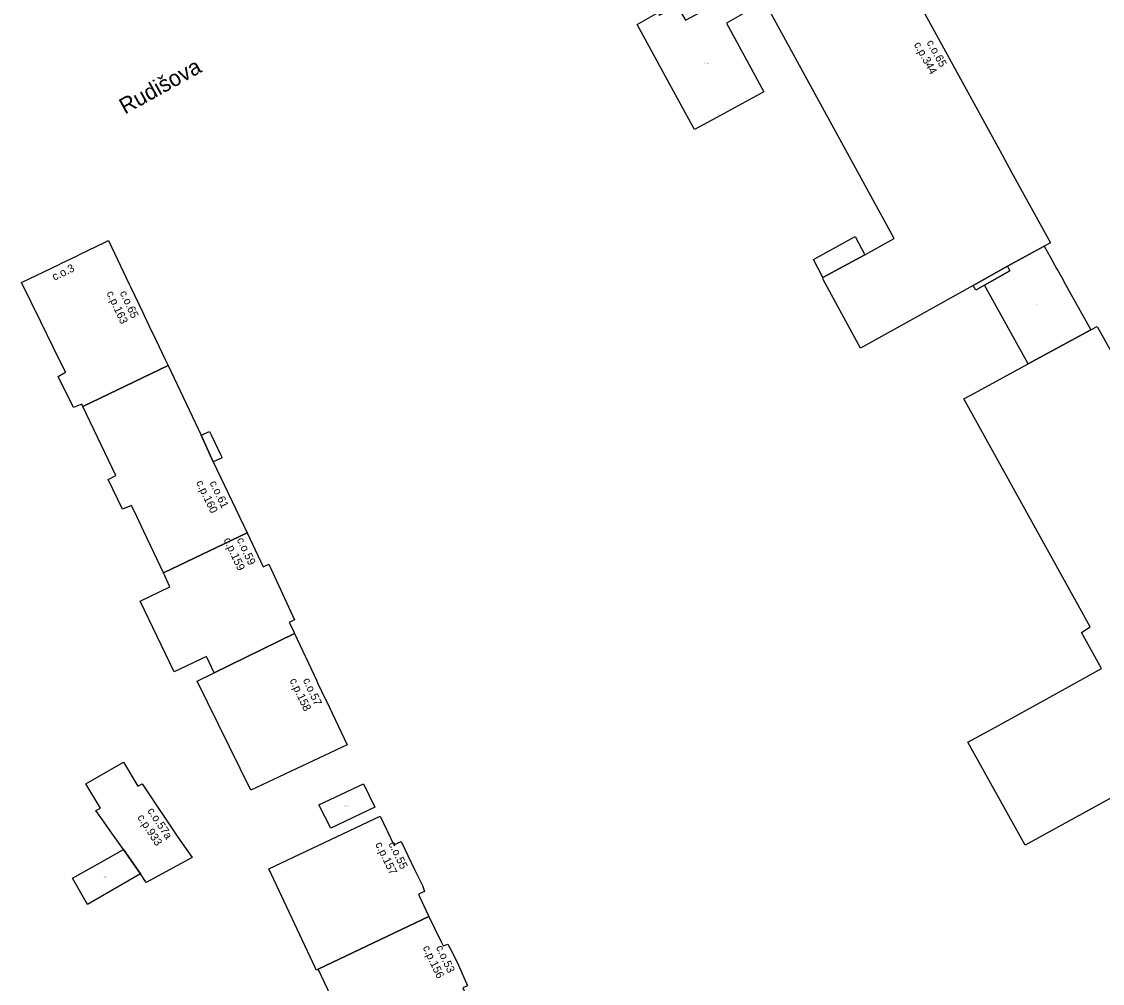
# Model space of a CAD drawing. Extents: x -600391 to -599491, y -1160176 to -1159402.
# Drawn here: x -600170.9 to -600035.9, y -1159941 to -1159820.9 of the extents above; entities that cross this region are included whole.
import ezdxf

# ---------------------------------------------------------------- set-up
doc = ezdxf.new("R2010")
doc.units = 0
for name, color, linetype in [('Level 10', 7, 'Continuous'), ('Level 11', 7, 'Continuous'), ('Level 12', 7, 'Continuous'), ('Level 24', 7, 'Continuous'), ('Level 25', 7, 'Continuous'), ('Level 61', 7, 'Continuous'), ('Level 62', 7, 'Continuous')]:
    doc.layers.add(name, color=color, linetype=linetype)

msp = doc.modelspace()

# ---------------------------------------------------------------- linework, layer by layer
at = {"layer": 'Level 61'}
for points in [[(-600079.35, -1159819.1), (-600082.86, -1159821.07)], [(-600063.12, -1159845.77), (-600078.08, -1159818.36)], [(-600058.78, -1159818.63), (-600048.7, -1159837.01)], [(-600094.02, -1159821.24), (-600091.37, -1159819.77)], [(-600088.71, -1159830.95), (-600094.02, -1159821.24)], [(-600082.86, -1159821.07), (-600080.07, -1159826.22)], [(-600080.07, -1159826.22), (-600078.2, -1159829.67)], [(-600078.2, -1159829.67), (-600084.15, -1159832.9)], [(-600086.85, -1159834.36), (-600088.71, -1159830.95)], [(-600084.15, -1159832.9), (-600086.85, -1159834.36)], [(-600048.7, -1159837.01), (-600047.23, -1159839.69)], [(-600047.23, -1159839.69), (-600042.39, -1159848.51)], [(-600061.89, -1159848), (-600063.12, -1159845.77)], [(-600071.97, -1159850.6), (-600066.76, -1159847.73)], [(-600066.76, -1159847.73), (-600065.55, -1159850.01)], [(-600065.55, -1159850.01), (-600061.89, -1159848)], [(-600163.65, -1159850), (-600160.45, -1159848.45)], [(-600160.45, -1159848.45), (-600160.03, -1159848.25)], [(-600160.03, -1159848.25), (-600157.44, -1159853.69)], [(-600043.18, -1159848.94), (-600047.74, -1159851.46)], [(-600047.74, -1159851.46), (-600043.18, -1159848.94)], [(-600042.39, -1159848.51), (-600043.18, -1159848.94)], [(-600043.18, -1159848.94), (-600042.43, -1159850.28)], [(-600165.88, -1159851.08), (-600163.96, -1159850.15)], [(-600163.96, -1159850.15), (-600163.65, -1159850)], [(-600070.83, -1159852.86), (-600071.97, -1159850.6)], [(-600070.83, -1159852.86), (-600065.55, -1159850.01)], [(-600065.55, -1159850.01), (-600070.83, -1159852.86)], [(-600042.43, -1159850.28), (-600041.62, -1159851.73)], [(-600170.88, -1159853.49), (-600166.2, -1159851.23)], [(-600166.2, -1159851.23), (-600165.88, -1159851.08)], [(-600052.02, -1159853.85), (-600047.74, -1159851.46)], [(-600047.74, -1159851.46), (-600052.02, -1159853.85)], [(-600047.45, -1159852.03), (-600050.61, -1159853.81)], [(-600050.61, -1159853.81), (-600047.45, -1159852.03)], [(-600047.74, -1159851.46), (-600047.45, -1159852.03)], [(-600047.45, -1159852.03), (-600047.74, -1159851.46)], [(-600041.62, -1159851.73), (-600041.47, -1159851.99)], [(-600041.47, -1159851.99), (-600040.81, -1159853.16)], [(-600070.77, -1159853.12), (-600070.83, -1159852.86)], [(-600066.1, -1159861.67), (-600070.77, -1159853.12)], [(-600040.81, -1159853.16), (-600040.67, -1159853.43)], [(-600040.67, -1159853.43), (-600037.35, -1159859.41)], [(-600168.48, -1159858.39), (-600170.88, -1159853.49)], [(-600157.44, -1159853.69), (-600157.28, -1159854.02)], [(-600157.28, -1159854.02), (-600155.74, -1159857.25)], [(-600052.02, -1159853.85), (-600058.91, -1159857.7)], [(-600051.72, -1159854.44), (-600052.02, -1159853.85)], [(-600050.61, -1159853.81), (-600051.72, -1159854.44)], [(-600045.16, -1159863.66), (-600050.61, -1159853.81)], [(-600155.74, -1159857.25), (-600155.57, -1159857.62)], [(-600166.88, -1159861.66), (-600168.48, -1159858.39)], [(-600155.57, -1159857.62), (-600154.61, -1159859.63)], [(-600058.91, -1159857.7), (-600066.1, -1159861.67)], [(-600154.61, -1159859.63), (-600154.46, -1159859.95)], [(-600154.46, -1159859.95), (-600152.96, -1159863.1)], [(-600037.35, -1159859.41), (-600045.16, -1159863.66)], [(-600045.16, -1159863.66), (-600037.35, -1159859.41)], [(-600037.35, -1159859.41), (-600036.54, -1159858.98)], [(-600036.54, -1159858.98), (-600029.35, -1159871.89)], [(-600165.39, -1159864.7), (-600166.88, -1159861.66)], [(-600152.59, -1159863.87), (-600163.24, -1159868.98)], [(-600163.24, -1159868.98), (-600152.59, -1159863.87)], [(-600152.96, -1159863.1), (-600152.8, -1159863.44)], [(-600152.8, -1159863.44), (-600152.59, -1159863.87)], [(-600152.59, -1159863.87), (-600148.47, -1159872.54)], [(-600051.89, -1159867.31), (-600045.16, -1159863.66)], [(-600166.31, -1159865.22), (-600165.39, -1159864.7)], [(-600164.39, -1159869.1), (-600166.31, -1159865.22)], [(-600053.19, -1159868.02), (-600051.89, -1159867.31)], [(-600037.41, -1159896.51), (-600053.19, -1159868.02)], [(-600163.38, -1159868.66), (-600164.39, -1159869.1)], [(-600163.24, -1159868.98), (-600163.38, -1159868.66)], [(-600159.12, -1159877.59), (-600163.24, -1159868.98)], [(-600148.47, -1159872.54), (-600147.41, -1159872.09)], [(-600147.41, -1159872.09), (-600147.2, -1159872.53)], [(-600146.95, -1159875.9), (-600148.47, -1159872.54)], [(-600148.47, -1159872.54), (-600146.95, -1159875.9)], [(-600147.2, -1159872.53), (-600146, -1159875.04)], [(-600146, -1159875.04), (-600145.82, -1159875.38)], [(-600145.82, -1159875.38), (-600146.95, -1159875.9)], [(-600146.95, -1159875.9), (-600142.71, -1159884.74)], [(-600160.05, -1159878.1), (-600159.12, -1159877.59)], [(-600158.3, -1159881.81), (-600160.05, -1159878.1)], [(-600157.17, -1159881.34), (-600158.3, -1159881.81)], [(-600156.5, -1159882.73), (-600157.17, -1159881.34)], [(-600155.62, -1159884.58), (-600156.5, -1159882.73)], [(-600153.15, -1159889.76), (-600155.62, -1159884.58)], [(-600142.71, -1159884.74), (-600153.15, -1159889.76)], [(-600153.15, -1159889.76), (-600142.71, -1159884.74)], [(-600142.71, -1159884.74), (-600140.71, -1159889)], [(-600152.38, -1159891.51), (-600153.15, -1159889.76)], [(-600140.71, -1159889), (-600140.02, -1159888.65)], [(-600140.02, -1159888.65), (-600136.8, -1159895.63)], [(-600156.06, -1159893.29), (-600152.38, -1159891.51)], [(-600151.82, -1159902.1), (-600156.06, -1159893.29)], [(-600136.8, -1159895.63), (-600137.46, -1159895.97)], [(-600137.46, -1159895.97), (-600136.9, -1159897.07)], [(-600038.5, -1159897.19), (-600037.41, -1159896.51)], [(-600136.78, -1159897.34), (-600146.82, -1159902.24)], [(-600146.82, -1159902.24), (-600136.78, -1159897.34)], [(-600136.9, -1159897.07), (-600136.78, -1159897.34)], [(-600136.78, -1159897.34), (-600134.02, -1159903.25)], [(-600036.01, -1159901.71), (-600038.5, -1159897.19)], [(-600147.81, -1159900.21), (-600151.82, -1159902.1)], [(-600146.82, -1159902.24), (-600147.81, -1159900.21)], [(-600040.15, -1159903.99), (-600036.01, -1159901.71)], [(-600148.94, -1159903.29), (-600146.82, -1159902.24)], [(-600142.24, -1159916.89), (-600148.94, -1159903.29)], [(-600134.02, -1159903.25), (-600133.91, -1159903.48)], [(-600133.91, -1159903.48), (-600132.92, -1159905.56)], [(-600042.46, -1159905.27), (-600040.15, -1159903.99)], [(-600132.92, -1159905.56), (-600132.82, -1159905.77)], [(-600132.82, -1159905.77), (-600130.21, -1159911.22)], [(-600046.85, -1159907.69), (-600042.46, -1159905.27)], [(-600049.25, -1159909.02), (-600046.85, -1159907.69)], [(-600052.69, -1159910.92), (-600049.25, -1159909.02)], [(-600130.21, -1159911.22), (-600142.24, -1159916.89)], [(-600045.53, -1159923.79), (-600052.69, -1159910.92)], [(-600162.86, -1159916.1), (-600158.15, -1159913.41)], [(-600158.15, -1159913.41), (-600156.35, -1159916.42)], [(-600027.98, -1159914.13), (-600045.53, -1159923.79)], [(-600161.04, -1159919.14), (-600162.86, -1159916.1)], [(-600156.35, -1159916.42), (-600155.83, -1159916.12)], [(-600155.83, -1159916.12), (-600154.16, -1159918.62)], [(-600133.75, -1159918.74), (-600128.2, -1159916.13)], [(-600128.2, -1159916.13), (-600126.76, -1159919.01)], [(-600161.59, -1159919.46), (-600161.04, -1159919.14)], [(-600160.57, -1159920.9), (-600161.59, -1159919.46)], [(-600154.16, -1159918.62), (-600152.79, -1159920.64)], [(-600132.26, -1159921.65), (-600133.75, -1159918.74)], [(-600126.76, -1159919.01), (-600132.26, -1159921.65)], [(-600159.8, -1159921.99), (-600160.57, -1159920.9)], [(-600152.79, -1159920.64), (-600151.37, -1159922.76)], [(-600140, -1159926.73), (-600126.12, -1159920.16)], [(-600126.12, -1159920.16), (-600124.38, -1159923.72)], [(-600158.37, -1159924.01), (-600159.8, -1159921.99)], [(-600151.37, -1159922.76), (-600149.6, -1159925.33)], [(-600124.38, -1159923.72), (-600123.49, -1159923.33)], [(-600123.49, -1159923.33), (-600121.81, -1159926.81)], [(-600161.03, -1159925.93), (-600158.17, -1159924.3)], [(-600158.17, -1159924.3), (-600158.37, -1159924.01)], [(-600156.89, -1159926.1), (-600158.17, -1159924.3)], [(-600158.17, -1159924.3), (-600156.89, -1159926.1)], [(-600164.53, -1159927.88), (-600161.03, -1159925.93)], [(-600156.05, -1159927.37), (-600156.89, -1159926.1)], [(-600156.89, -1159926.1), (-600156.05, -1159927.37)], [(-600149.6, -1159925.33), (-600155.33, -1159928.45)], [(-600156.05, -1159927.37), (-600162.67, -1159931.18)], [(-600155.33, -1159928.45), (-600156.05, -1159927.37)], [(-600134.22, -1159939.05), (-600140, -1159926.73)], [(-600121.81, -1159926.81), (-600120.83, -1159928.82)], [(-600162.67, -1159931.18), (-600164.53, -1159927.88)], [(-600120.83, -1159928.82), (-600120.57, -1159929.54)], [(-600120.57, -1159929.54), (-600121.33, -1159929.88)], [(-600121.33, -1159929.88), (-600121.2, -1159930.2)], [(-600121.2, -1159930.2), (-600120.35, -1159931.98)], [(-600120.02, -1159932.67), (-600133.83, -1159939.26)], [(-600133.83, -1159939.26), (-600120.02, -1159932.67)], [(-600120.35, -1159931.98), (-600120.02, -1159932.67)], [(-600120.02, -1159932.67), (-600118.52, -1159935.78)], [(-600118.52, -1159935.78), (-600118.25, -1159936.35)], [(-600118.25, -1159936.35), (-600117.63, -1159936.13)], [(-600117.63, -1159936.13), (-600117.07, -1159937.23)], [(-600117.07, -1159937.23), (-600116.33, -1159938.77)], [(-600134.1, -1159939.39), (-600134.22, -1159939.05)], [(-600133.83, -1159939.26), (-600134.1, -1159939.39)], [(-600127.84, -1159951.9), (-600133.83, -1159939.26)], [(-600116.33, -1159938.77), (-600115.19, -1159941.35)]]:
    msp.add_lwpolyline(points, dxfattribs=at)
at = {"layer": 'Level 62'}
for points in [[(-600079.35, -1159819.1), (-600082.86, -1159821.07), (-600080.07, -1159826.22), (-600078.2, -1159829.67), (-600084.15, -1159832.9), (-600086.85, -1159834.36), (-600088.71, -1159830.95), (-600094.02, -1159821.24), (-600091.37, -1159819.77), (-600091.21, -1159820.1), (-600089, -1159818.94), (-600087.98, -1159820.71), (-600080.6, -1159816.74), (-600079.35, -1159819.1)], [(-600058.78, -1159818.63), (-600048.7, -1159837.01), (-600047.23, -1159839.69), (-600042.39, -1159848.51), (-600043.18, -1159848.94), (-600047.74, -1159851.46), (-600052.02, -1159853.85), (-600058.91, -1159857.7), (-600066.1, -1159861.67), (-600070.77, -1159853.12), (-600070.83, -1159852.86), (-600065.55, -1159850.01), (-600061.89, -1159848), (-600063.12, -1159845.77), (-600078.08, -1159818.36)], [(-600066.76, -1159847.73), (-600065.55, -1159850.01), (-600070.83, -1159852.86), (-600071.97, -1159850.6), (-600066.76, -1159847.73)], [(-600163.24, -1159868.98), (-600163.38, -1159868.66), (-600164.39, -1159869.1), (-600166.31, -1159865.22), (-600165.39, -1159864.7), (-600166.88, -1159861.66), (-600168.48, -1159858.39), (-600170.88, -1159853.49), (-600166.2, -1159851.23), (-600165.88, -1159851.08), (-600163.96, -1159850.15), (-600163.65, -1159850), (-600160.45, -1159848.45), (-600160.03, -1159848.25), (-600157.44, -1159853.69), (-600157.28, -1159854.02), (-600155.74, -1159857.25), (-600155.57, -1159857.62), (-600154.61, -1159859.63), (-600154.46, -1159859.95), (-600152.96, -1159863.1), (-600152.8, -1159863.44), (-600152.59, -1159863.87), (-600163.24, -1159868.98)], [(-600045.16, -1159863.66), (-600050.61, -1159853.81), (-600047.45, -1159852.03), (-600047.74, -1159851.46), (-600043.18, -1159848.94), (-600042.43, -1159850.28), (-600041.62, -1159851.73), (-600041.47, -1159851.99), (-600040.81, -1159853.16), (-600040.67, -1159853.43), (-600037.35, -1159859.41), (-600045.16, -1159863.66)], [(-600050.61, -1159853.81), (-600051.72, -1159854.44), (-600052.02, -1159853.85), (-600047.74, -1159851.46), (-600047.45, -1159852.03), (-600050.61, -1159853.81)], [(-600027.98, -1159914.13), (-600045.53, -1159923.79), (-600052.69, -1159910.92), (-600049.25, -1159909.02), (-600046.85, -1159907.69), (-600042.46, -1159905.27), (-600040.15, -1159903.99), (-600036.01, -1159901.71), (-600038.5, -1159897.19), (-600037.41, -1159896.51), (-600053.19, -1159868.02), (-600051.89, -1159867.31), (-600045.16, -1159863.66), (-600037.35, -1159859.41), (-600036.54, -1159858.98), (-600029.35, -1159871.89)], [(-600142.71, -1159884.74), (-600153.15, -1159889.76), (-600155.62, -1159884.58), (-600156.5, -1159882.73), (-600157.17, -1159881.34), (-600158.3, -1159881.81), (-600160.05, -1159878.1), (-600159.12, -1159877.59), (-600163.24, -1159868.98), (-600152.59, -1159863.87), (-600148.47, -1159872.54), (-600146.95, -1159875.9), (-600142.71, -1159884.74)], [(-600148.47, -1159872.54), (-600147.41, -1159872.09), (-600147.2, -1159872.53), (-600146, -1159875.04), (-600145.82, -1159875.38), (-600146.95, -1159875.9), (-600148.47, -1159872.54)], [(-600146.82, -1159902.24), (-600147.81, -1159900.21), (-600151.82, -1159902.1), (-600156.06, -1159893.29), (-600152.38, -1159891.51), (-600153.15, -1159889.76), (-600142.71, -1159884.74), (-600140.71, -1159889), (-600140.02, -1159888.65), (-600136.8, -1159895.63), (-600137.46, -1159895.97), (-600136.9, -1159897.07), (-600136.78, -1159897.34), (-600146.82, -1159902.24)], [(-600146.82, -1159902.24), (-600136.78, -1159897.34), (-600134.02, -1159903.25), (-600133.91, -1159903.48), (-600132.92, -1159905.56), (-600132.82, -1159905.77), (-600130.21, -1159911.22), (-600142.24, -1159916.89), (-600148.94, -1159903.29), (-600146.82, -1159902.24)], [(-600155.83, -1159916.12), (-600154.16, -1159918.62), (-600152.79, -1159920.64), (-600151.37, -1159922.76), (-600149.6, -1159925.33), (-600155.33, -1159928.45), (-600156.05, -1159927.37), (-600156.89, -1159926.1), (-600158.17, -1159924.3), (-600158.37, -1159924.01), (-600159.8, -1159921.99), (-600160.57, -1159920.9), (-600161.59, -1159919.46), (-600161.04, -1159919.14), (-600162.86, -1159916.1), (-600158.15, -1159913.41), (-600156.35, -1159916.42), (-600155.83, -1159916.12)], [(-600126.76, -1159919.01), (-600132.26, -1159921.65), (-600133.75, -1159918.74), (-600128.2, -1159916.13), (-600126.76, -1159919.01)], [(-600120.83, -1159928.82), (-600120.57, -1159929.54), (-600121.33, -1159929.88), (-600121.2, -1159930.2), (-600120.35, -1159931.98), (-600120.02, -1159932.67), (-600133.83, -1159939.26), (-600134.1, -1159939.39), (-600134.22, -1159939.05), (-600140, -1159926.73), (-600126.12, -1159920.16), (-600124.38, -1159923.72), (-600123.49, -1159923.33), (-600121.81, -1159926.81), (-600120.83, -1159928.82)], [(-600158.17, -1159924.3), (-600156.89, -1159926.1), (-600156.05, -1159927.37), (-600162.67, -1159931.18), (-600164.53, -1159927.88), (-600161.03, -1159925.93), (-600158.17, -1159924.3)], [(-600120.02, -1159932.67), (-600118.52, -1159935.78), (-600118.25, -1159936.35), (-600117.63, -1159936.13), (-600117.07, -1159937.23), (-600116.33, -1159938.77), (-600115.19, -1159941.35), (-600115.79, -1159941.59), (-600113.99, -1159945.44), (-600126.93, -1159951.47), (-600127.84, -1159951.9), (-600133.83, -1159939.26), (-600120.02, -1159932.67)]]:
    msp.add_lwpolyline(points, dxfattribs=at)

# ---------------------------------------------------------------- texts
at = {"layer": 'Level 10'}
for s, rotation, p in [('c.o.65', 298.7435, (-600057.89, -1159823.49)), ('c.o.3', 25.6067, (-600166.79, -1159853.27)), ('c.o.65', 294.9556, (-600158.65, -1159854.76)), ('c.o.61', 295.6015, (-600147.43, -1159878.51)), ('c.o.59', 295.0941, (-600144.03, -1159885.6)), ('c.o.57', 295.1121, (-600135.78, -1159903.15)), ('c.o.57a', 303.3119, (-600155.22, -1159919.47)), ('c.o.55', 295.8501, (-600125.09, -1159923.6)), ('c.o.53', 295.0557, (-600119.16, -1159936.54))]:
    msp.add_text(s, height=1, rotation=rotation, dxfattribs=at).set_placement(p)
at = {"layer": 'Level 11'}
msp.add_text('Rudišova', height=2, rotation=29.0141, dxfattribs=at).set_placement((-600157.98, -1159832.52))
at = {"layer": 'Level 12'}
for s, rotation, p in [('c.p.344', 298.7435, (-600059.47, -1159823.74)), ('c.p.163', 294.9556, (-600160.3, -1159854.79)), ('c.p.160', 295.6015, (-600149.12, -1159878.46)), ('c.p.159', 295.0941, (-600145.68, -1159885.62)), ('c.p.158', 295.1121, (-600137.43, -1159903.17)), ('c.p.933', 303.3119, (-600156.48, -1159920.3)), ('c.p.157', 295.8501, (-600126.74, -1159923.65)), ('c.p.156', 295.0557, (-600120.81, -1159936.56))]:
    msp.add_text(s, height=1, rotation=rotation, dxfattribs=at).set_placement(p)
at = {"layer": 'Level 24'}
for s, p in [('c.z.221', (-600044.34, -1159856.27)), ('c.z.189', (-600160.72, -1159927.78))]:
    msp.add_text(s, height=0.1, dxfattribs=at).set_placement(p)
at = {"layer": 'Level 25'}
for s, p in [('c.pp.344_A', (-600085.6, -1159826.11)), ('c.pp.157_A', (-600130.55, -1159918.9))]:
    msp.add_text(s, height=0.1, dxfattribs=at).set_placement(p)

doc.saveas('drawing.dxf')
